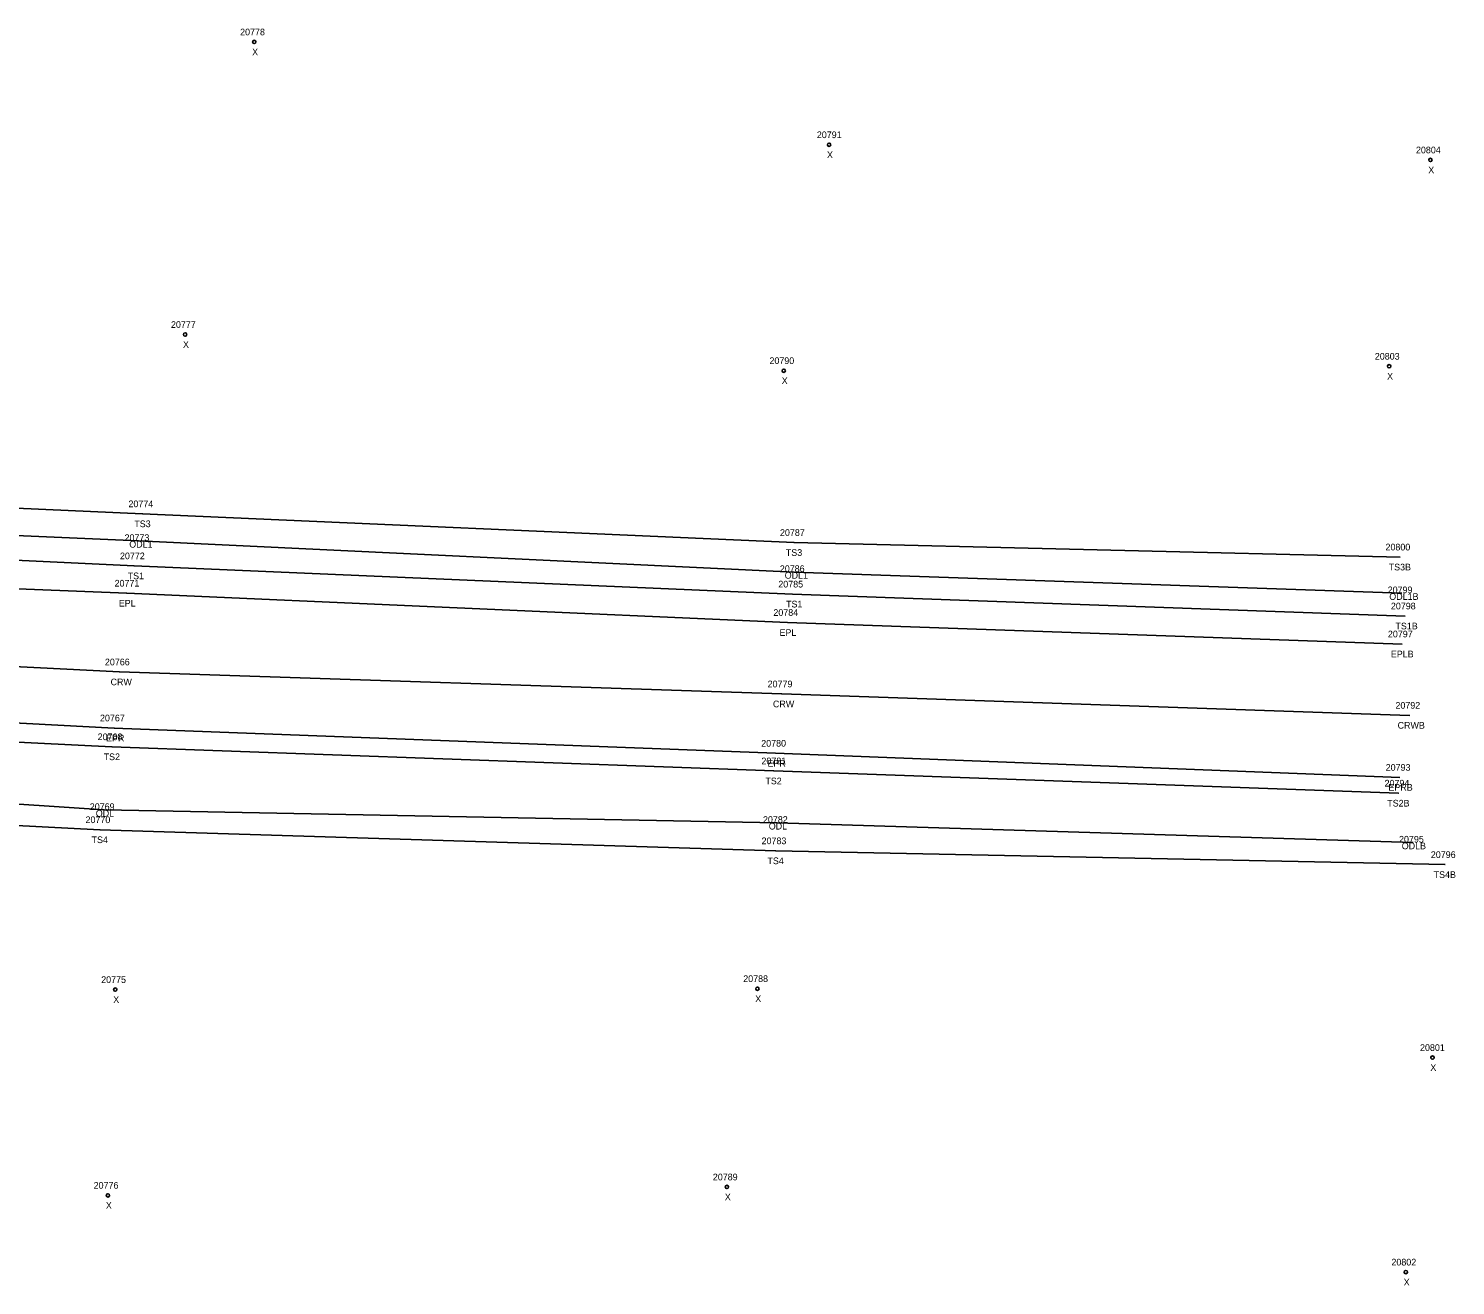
# Model space of a CAD drawing. Extents: x 1966740 to 1969291, y 1117378 to 1118461.
# Drawn here: x 1969077.2 to 1969291.3, y 1117799.2 to 1117987.8 of the extents above; entities that cross this region are included whole.
import ezdxf

# ---------------------------------------------------------------- set-up
doc = ezdxf.new("R2010")
doc.units = 0
for name, color, linetype in [('RD_DTM_BkLn1', 7, 'Continuous'), ('RD_DTM_BkLn2', 7, 'Continuous'), ('RD_EX_H2O', 7, 'Continuous'), ('RD_EX_H2O_txCode', 7, 'Continuous'), ('RD_EX_Road', 7, 'Continuous'), ('RD_EX_Road_txCode', 7, 'Continuous'), ('RD_SMD_Locator', 7, 'Continuous'), ('RD_SMD_Misc', 7, 'Continuous')]:
    doc.layers.add(name, color=color, linetype=linetype)

msp = doc.modelspace()

# ---------------------------------------------------------------- linework, layer by layer
at = {"layer": 'RD_DTM_BkLn1'}
msp.add_lwpolyline([(1968529.36, 1117916.3), (1968681.48, 1117908.5), (1968781.89, 1117904.51), (1968887.49, 1117900.39), (1968989.06, 1117896.4), (1969090.87, 1117891.24), (1969190.23, 1117887.94), (1969284.4, 1117884.73)], dxfattribs=at)
at = {"layer": 'RD_DTM_BkLn2'}
for points in [[(1968531.49, 1117931.42), (1968682.06, 1117924.3), (1968783.42, 1117919.17), (1968888.7, 1117914.33), (1968991.06, 1117912.02), (1969093.07, 1117907.16), (1969191.83, 1117902.92), (1969283.72, 1117899.63)], [(1968882.13, 1117923.29), (1968991.72, 1117919.56), (1969094.35, 1117914.97), (1969192.08, 1117910.66), (1969282.99, 1117908.48)], [(1968528.99, 1117899.6), (1968680.45, 1117894.84), (1968781.74, 1117892.71), (1968887.7, 1117888.94), (1968987.81, 1117885.08), (1969089.75, 1117880.01), (1969189.02, 1117876.39), (1969282.76, 1117873.05)], [(1968528.68, 1117880.51), (1968680.3, 1117884.55), (1968781.05, 1117880.46), (1968887.57, 1117875.57), (1968986, 1117872.85), (1969087.95, 1117867.56), (1969189.32, 1117864.4), (1969289.73, 1117862.33)]]:
    msp.add_lwpolyline(points, dxfattribs=at)
at = {"layer": 'RD_EX_H2O'}
for points in [[(1968531.76, 1117937.18), (1968682.22, 1117928.11), (1968784.28, 1117924.56), (1968890.2, 1117919.49), (1968991.22, 1117915.37), (1969093.76, 1117910.9), (1969192.08, 1117906.24), (1969283.24, 1117903.06)], [(1968528.55, 1117888.35), (1968679.78, 1117887.39), (1968780.67, 1117884.45), (1968887.36, 1117880.9), (1968987.02, 1117877.31), (1969088.58, 1117870.53), (1969189.53, 1117868.6), (1969284.94, 1117865.64)]]:
    msp.add_lwpolyline(points, dxfattribs=at)
at = {"layer": 'RD_EX_Road'}
for points in [[(1968530.54, 1117925.7), (1968681.97, 1117919.01), (1968783.23, 1117915.36), (1968888.64, 1117911.44), (1968991.22, 1117907.09), (1969091.98, 1117903.06), (1969191.09, 1117898.66), (1969283.27, 1117895.43)], [(1968527.82, 1117906.41), (1968680.79, 1117899.07), (1968781.71, 1117895.37), (1968887.86, 1117891.84), (1968988.65, 1117888.23), (1969090.1, 1117882.83), (1969189.3, 1117879.04), (1969282.94, 1117875.42)]]:
    msp.add_lwpolyline(points, dxfattribs=at)
at = {"layer": 'RD_SMD_Locator'}
for centre, radius in [((1969111.1, 1117985.78), 0.25), ((1969197.32, 1117970.35), 0.25), ((1969287.52, 1117968.07), 0.25), ((1969100.72, 1117941.88), 0.25), ((1969190.53, 1117936.45), 0.25), ((1969281.34, 1117937.11), 0.25), ((1969094.35, 1117914.97), 0.001), ((1969093.76, 1117910.9), 0.001), ((1969192.08, 1117910.66), 0.001), ((1969282.99, 1117908.48), 0.001), ((1969093.07, 1117907.16), 0.001), ((1969192.08, 1117906.24), 0.001), ((1969091.98, 1117903.06), 0.001), ((1969191.83, 1117902.92), 0.001), ((1969283.24, 1117903.06), 0.001), ((1969283.72, 1117899.63), 0.001), ((1969191.09, 1117898.66), 0.001), ((1969283.27, 1117895.43), 0.001), ((1969090.87, 1117891.24), 0.001), ((1969190.23, 1117887.94), 0.001), ((1969284.4, 1117884.73), 0.001), ((1969090.1, 1117882.83), 0.001), ((1969089.75, 1117880.01), 0.001), ((1969189.3, 1117879.04), 0.001), ((1969189.02, 1117876.39), 0.001), ((1969282.94, 1117875.42), 0.001), ((1969282.76, 1117873.05), 0.001), ((1969088.58, 1117870.53), 0.001), ((1969087.95, 1117867.56), 0.001), ((1969189.53, 1117868.6), 0.001), ((1969284.94, 1117865.64), 0.001), ((1969189.32, 1117864.4), 0.001), ((1969289.73, 1117862.33), 0.001), ((1969090.26, 1117843.58), 0.25), ((1969186.57, 1117843.71), 0.25), ((1969287.84, 1117833.38), 0.25), ((1969182.01, 1117813.96), 0.25), ((1969089.15, 1117812.7), 0.25), ((1969283.84, 1117801.18), 0.25)]:
    msp.add_circle(centre, radius, dxfattribs=at)

# ---------------------------------------------------------------- texts
at = {"layer": 'RD_EX_H2O_txCode'}
for s, p in [('20773', (1969091.64, 1117910.9)), ('ODL1', (1969092.35, 1117909.9)), ('20786', (1969189.94, 1117906.24)), ('ODL1', (1969190.67, 1117905.24)), ('20799', (1969281.12, 1117903.06)), ('ODL1B', (1969281.36, 1117902.06)), ('20769', (1969086.43, 1117870.53)), ('ODL', (1969087.33, 1117869.53)), ('20782', (1969187.41, 1117868.6)), ('ODL', (1969188.28, 1117867.6)), ('20795', (1969282.82, 1117865.64)), ('ODLB', (1969283.23, 1117864.64))]:
    msp.add_text(s, height=1, dxfattribs=at).set_placement(p)
at = {"layer": 'RD_EX_Road_txCode'}
for s, p in [('20771', (1969090.15, 1117904.06)), ('EPL', (1969090.78, 1117901.06)), ('20784', (1969188.97, 1117899.66)), ('EPL', (1969189.89, 1117896.66)), ('20797', (1969281.15, 1117896.43)), ('EPLB', (1969281.59, 1117893.43)), ('20767', (1969087.96, 1117883.83)), ('EPR', (1969088.87, 1117880.83)), ('20780', (1969187.15, 1117880.04)), ('EPR', (1969188.08, 1117877.04)), ('20793', (1969280.82, 1117876.42)), ('EPRB', (1969281.23, 1117873.42))]:
    msp.add_text(s, height=1, dxfattribs=at).set_placement(p)
at = {"layer": 'RD_SMD_Misc'}
for s, p in [('20778', (1969108.98, 1117986.78)), ('X', (1969110.78, 1117983.78)), ('20791', (1969195.49, 1117971.35)), ('20804', (1969285.36, 1117969.07)), ('X', (1969197.01, 1117968.35)), ('X', (1969287.21, 1117966.07)), ('20777', (1969098.61, 1117942.88)), ('X', (1969100.41, 1117939.88)), ('20790', (1969188.38, 1117937.45)), ('20803', (1969279.19, 1117938.11)), ('X', (1969281.03, 1117935.11)), ('X', (1969190.22, 1117934.45)), ('20774', (1969092.23, 1117915.97)), ('TS3', (1969093.11, 1117912.97)), ('20787', (1969189.96, 1117911.66)), ('20800', (1969280.79, 1117909.48)), ('20772', (1969090.96, 1117908.16)), ('TS3', (1969190.84, 1117908.66)), ('TS1', (1969092.11, 1117905.16)), ('TS3B', (1969281.27, 1117906.48)), ('20785', (1969189.71, 1117903.92)), ('TS1', (1969190.87, 1117900.92)), ('20798', (1969281.6, 1117900.63)), ('TS1B', (1969282.28, 1117897.63)), ('20766', (1969088.7, 1117892.24)), ('CRW', (1969089.55, 1117889.24)), ('20779', (1969188.11, 1117888.94)), ('CRW', (1969188.91, 1117885.94)), ('20792', (1969282.28, 1117885.73)), ('CRWB', (1969282.61, 1117882.73)), ('20768', (1969087.61, 1117881.01)), ('TS2', (1969088.51, 1117878.01)), ('20781', (1969187.18, 1117877.39)), ('TS2', (1969187.77, 1117874.39)), ('20794', (1969280.65, 1117874.05)), ('TS2B', (1969281.05, 1117871.05)), ('20770', (1969085.79, 1117868.56)), ('TS4', (1969086.7, 1117865.56)), ('20783', (1969187.2, 1117865.4)), ('TS4', (1969188.08, 1117862.4)), ('20796', (1969287.59, 1117863.33)), ('TS4B', (1969288.01, 1117860.33)), ('20775', (1969088.14, 1117844.58)), ('20788', (1969184.45, 1117844.71)), ('X', (1969089.95, 1117841.58)), ('X', (1969186.25, 1117841.71)), ('20801', (1969285.97, 1117834.38)), ('X', (1969287.52, 1117831.38)), ('20789', (1969179.89, 1117814.96)), ('20776', (1969087.01, 1117813.7)), ('X', (1969088.84, 1117810.7)), ('X', (1969181.69, 1117811.96)), ('20802', (1969281.68, 1117802.18)), ('X', (1969283.52, 1117799.18))]:
    msp.add_text(s, height=1, dxfattribs=at).set_placement(p)

doc.saveas('drawing.dxf')
